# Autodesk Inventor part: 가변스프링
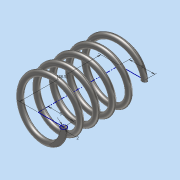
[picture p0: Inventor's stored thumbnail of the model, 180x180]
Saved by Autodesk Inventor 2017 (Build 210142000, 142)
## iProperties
Part Number: 가변스프링
Material: 스테인레스 스틸
Document SubType Name: Modeling
Designer: MRC
Density: 8 g/cm^3
Appearance: 반연마
Mass: 6.99701 g
Surface Area: 17.7559 cm^2
Volume: 0.874626 cm^3
Author: MRC
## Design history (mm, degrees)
sketch "스케치1"
  geometry: L1 (0, 0)-(0, 28.5); L2 (0, 28.5)-(9, 28.5); L3 (0, 0)-(9, 0); C1 r 1 at (9, 0)
  constraints: 6 end point, 2 horizontal, 1 centre point, 1 coincident, 1 vertical
  dimensions: "d0" = 28.5 distance of L1.start L1.end (derived); "d1" = 9 distance of L1.end L2.end; "d2" = 9 distance of L1.start L3.end; "d3" = 2 diameter of C1
feature "코일1" sketch "스케치1" pitch "d4" = 10; turns "d6" = 5; dims "d5" = 28.5 (= d0), "d7" = 0, angle "d8" = 90 deg, angle "d9" = 90 deg, "d10" = 0, "d11" = 0
sketch "스케치2"
  geometry: L1 (28.5, 15)-(0, 15); L2 (0, 15)-(0, -15); L3 (0, -15)-(28.5, -15); L4 (28.5, -15)-(28.5, 15); 2 further points
  constraints: 8 end point, 2 parallel, 1 coincident, 1 horizontal, 1 midpoint, 1 perpendicular
  dimensions: "d12" = 28.5 distance of L2.end L3.end (= d0); "d13" = 30 distance of L3.end L1.start
extrude "돌출1" sketch "스케치2" stored distance "d14" = 0; taper "d15" = 0 deg
node "솔리드1"
